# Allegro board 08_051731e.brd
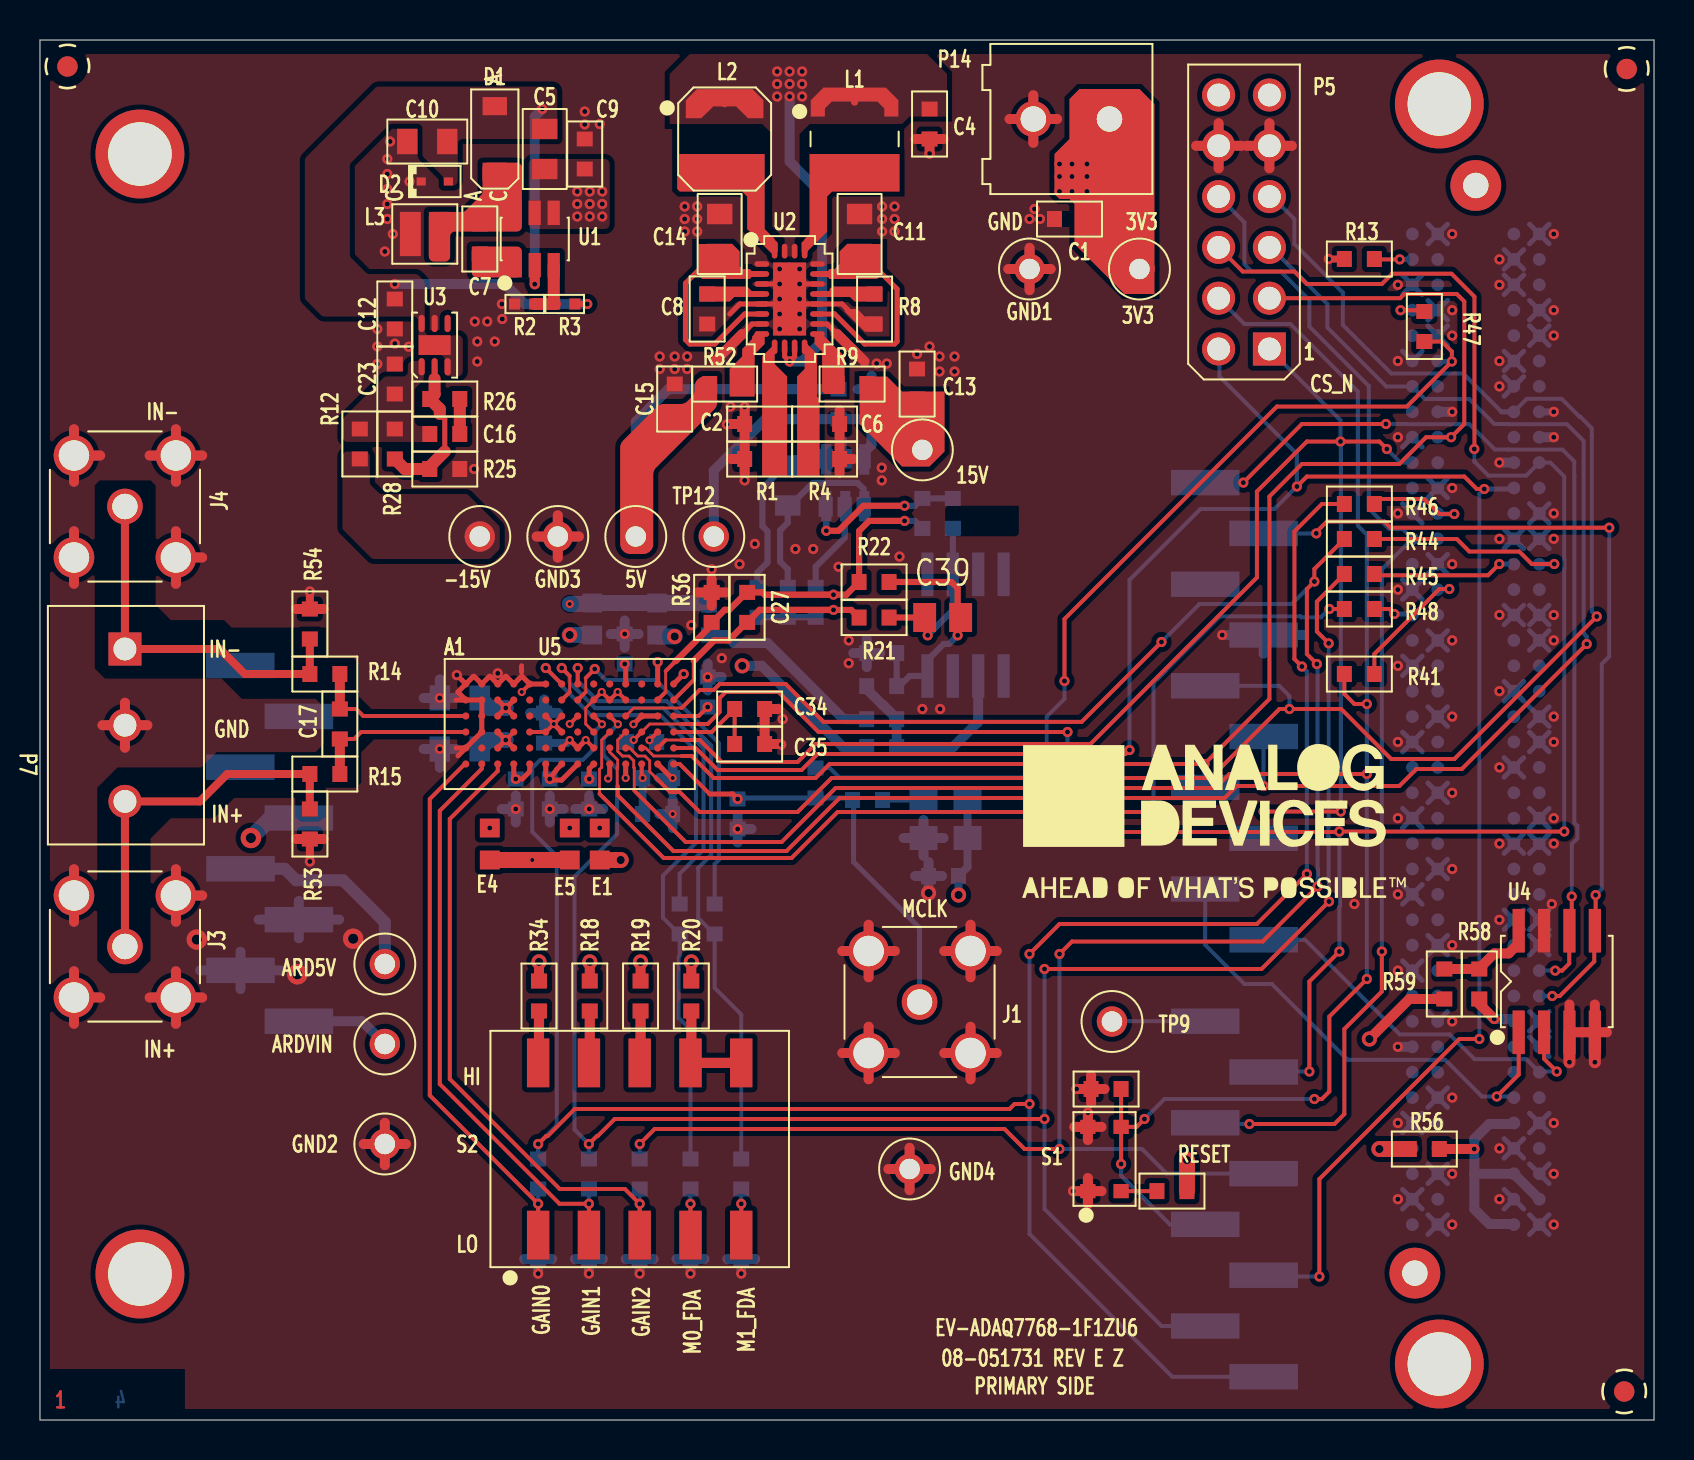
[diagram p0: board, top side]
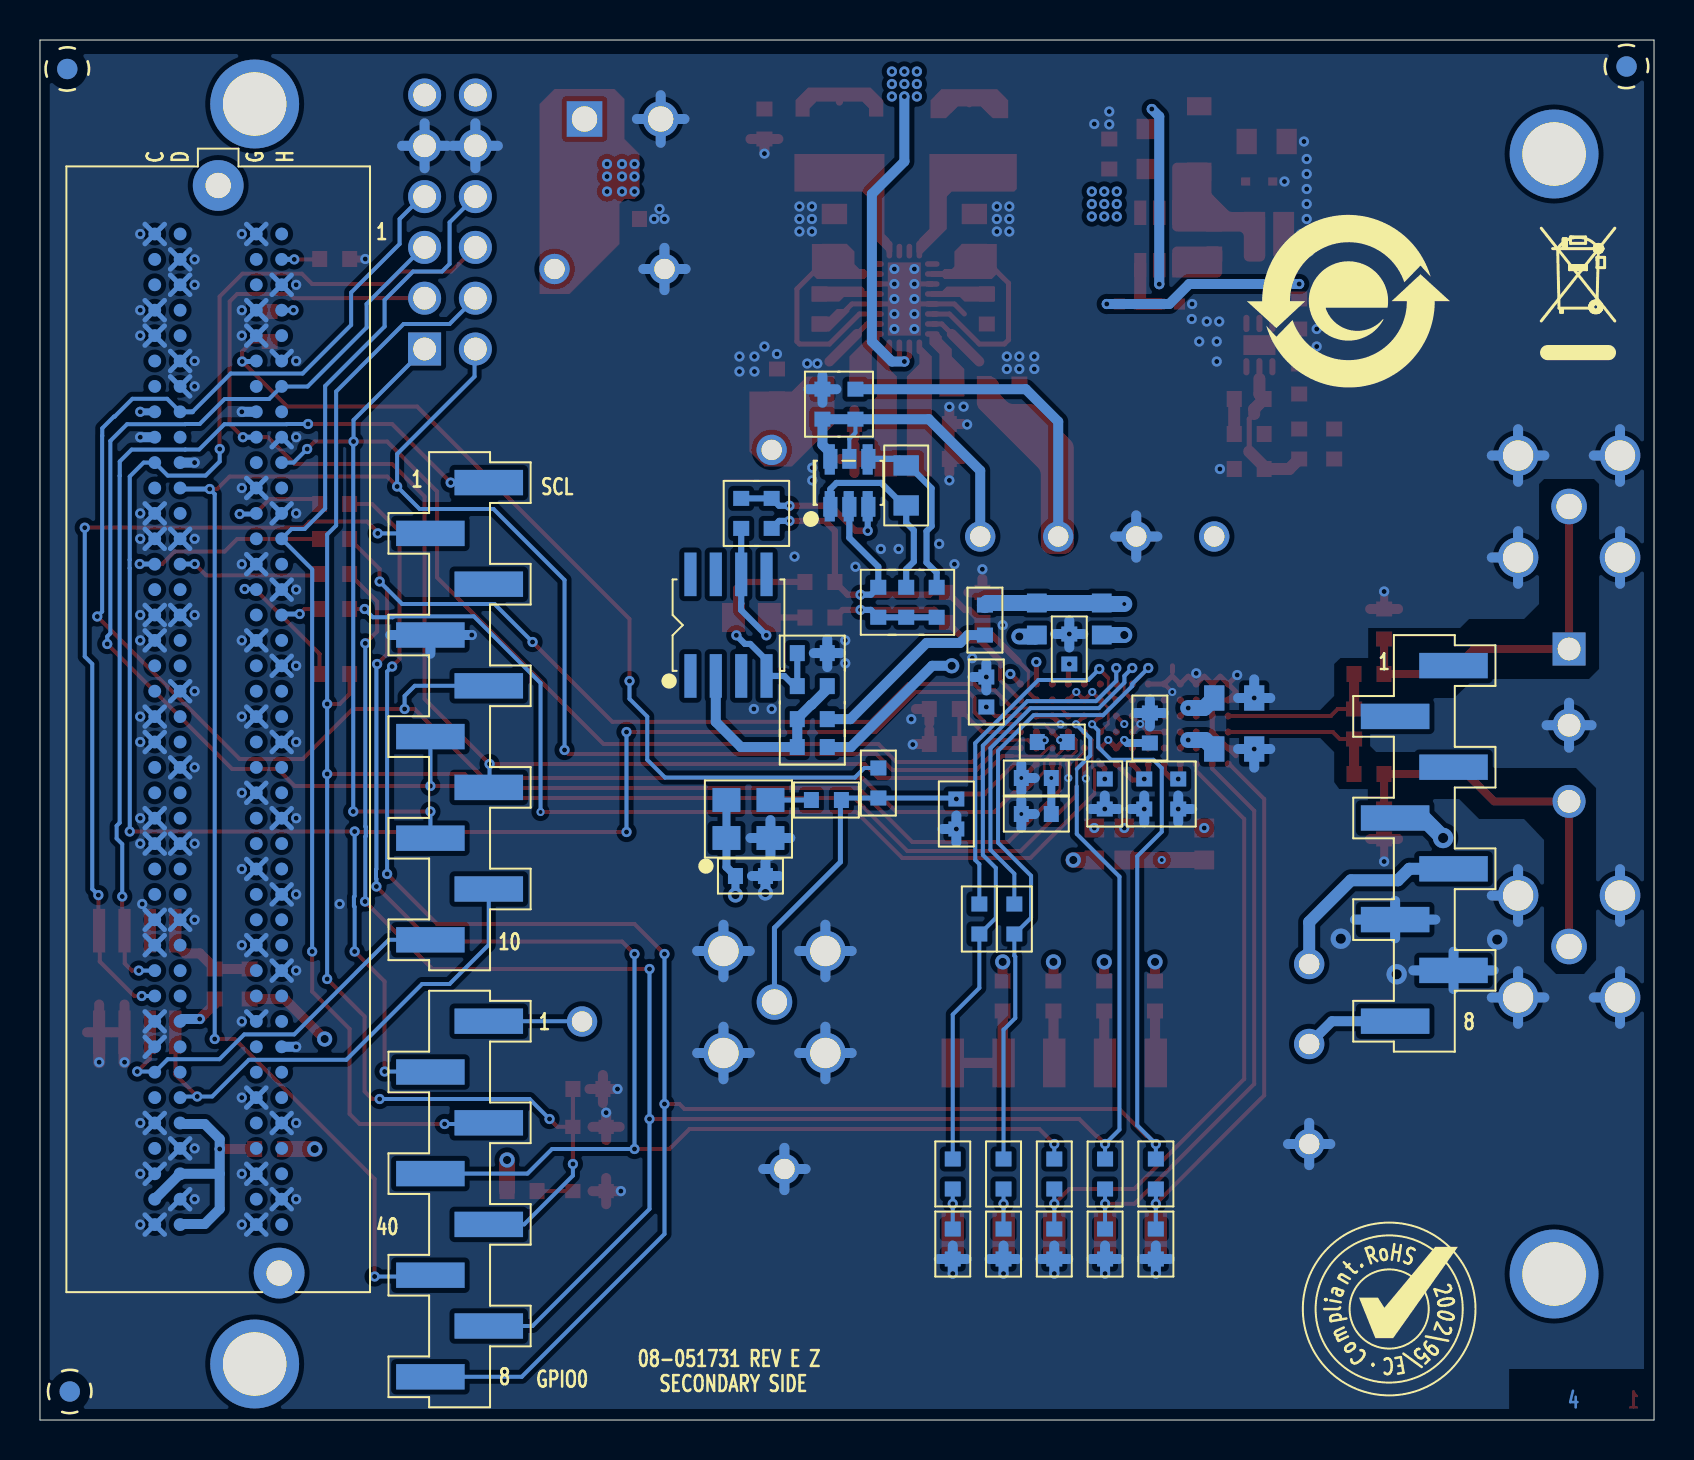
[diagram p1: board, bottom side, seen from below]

Outline 80.74 x 69 mm; copper layers: TOP, L2_GND, L3_PWR, BOTTOM. Coordinates in mm from the lower left corner of the outline.
Outline path: 0,69 80.74,69 80.74,0 0,0 0,69

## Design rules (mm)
constraint set DEFAULT: 
net group GAIN0: nets GAIN0 GPIO0
net group GAIN1: nets GAIN1 GPIO1
net group GAIN2: nets GAIN2 GPIO2
net group IN-N: nets IN-N IN-P
net group M0: nets M0 UNNAMED_3_RES_I311_N1
net group M1: nets M1 UNNAMED_3_RES_I312_N1
net group SYNC_IN: nets SYNC_IN UNNAMED_6_CN8PA_I42_N1
net group -16V: nets UNNAMED_3_ADP2301_I180_FB
net group REF_N: nets +IN -IN REF_N REF_P UNNAMED_3_ADR45XX_I443_VOUT VOUT
net group UNNAMED_3_ADP7182V5_I211_ADJ: nets UNNAMED_3_ADP7182V5_I211_ADJ UNNAMED_3_ADP7182V5_I211_VOUT UNNAMED_3_CAP_I209_N1

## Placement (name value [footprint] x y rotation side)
A1  ADA4807-1ARJZ  [SOT23_6-2]  40.25 46.86 180 bottom
A2  AD8628AUJZ  [TSOT-5]  40.28 46.86 180 bottom
ARD5V  RED  [CNKEY5001TP]  17.25 22.8 0 top
ARDVIN  RED  [CNKEY5001TP]  17.25 18.8 0 top
C1  1uF  [C0603]  51.5 60.05 180 top
C2  0.1uF  [C0603]  36 49.8 180 top
C3  TBD0603  [C0603]  34.9 30.3 270 bottom
C4  2.2uF  [C0603]  44.5 64.8 270 top
C5  1uF  [C0805H60]  25.25 63.55 90 top
C6  0.1uF  [C0603]  39.25 49.8 0 top
C7  0.1uF  [C0603]  22 59.05 90 top
C8  0.1uF  [C0603]  33.38 55.55 90 top
C9  1uF  [C0603]  27.25 63.3 90 top
C10  4.7uF  [C0805H53]  19.38 63.93 0 top
C11  10uF  [C0805H60]  41 59.3 90 top
C12  2.2uF  [C0603]  17.75 55.3 270 top
C13  2.2uF  [C0603]  43.88 51.8 90 top
C14  10uF  [C0805H60]  34 59.3 90 top
C15  2.2uF  [C0603]  31.75 51.05 90 top
C16  0.1uF  [C0603]  20.25 49.3 180 top
C17  TBD0603  [C0603]  15 34.8 270 top
C18  1uF  [C0805H60]  21 33.55 180 bottom
C19  1uF  [C0805H60]  21 36.1 180 bottom
C20  0.1uF  [C0603]  41.6 50.79 90 bottom
C21  TBD0603  [C0603]  25.5 31.3 270 bottom
C22  TBD0603  [C0603]  23.8 31.3 270 bottom
C23  2.2uF  [C0603]  17.75 52.05 90 top
C24  TBD0603  [C0603]  25.22 34.6 90 bottom
C25  0.1uF  [C0603]  45.2 27.2 180 bottom
C26  TBD0603  [C0603]  38.8 40.89 90 bottom
C27  2.2uF  [C0603]  35.38 40.63 90 top
C28  TBD0603  [C0603]  29.25 38.55 90 bottom
C29  TBD0603  [C0603]  33.4 36.4 90 bottom
C30  0.1uF  [C0603]  27.48 31.3 90 bottom
C34  0.1uF  [C0603]  35.5 35.55 0 top
C35  1uF  [C0603]  35.5 33.8 0 top
C36  0.1uF  [C0603]  30.9 30.3 0 bottom
C38  1uF  [C0603]  30.9 32.1 0 bottom
C39  1uF  [C0805]  45.16 40.12 0 top
C40  1uF  [C0603]  42.11 36.69 0 bottom
C44  0.1uF  [C0603]  53.33 16.55 180 top
C53  TBD0603  [C0603]  44.14 45.33 270 bottom
C54  3.9uF  [C0805H53]  37.41 46.73 270 bottom
D1  MBR0520LT1G  [SOD123-2]  22.75 64.05 90 top
D2  RB520S30T5G  [SOD523]  19.75 61.93 0 top
E1  1000OHM AT 100MEGHz  [L0603]  28 28.8 270 top
E2  1000OHM AT 100MEGHz  [L0603]  27.62 40.05 90 bottom
E3  1000OHM AT 100MEGHz  [L0603]  30.88 40.05 90 bottom
E4  1000OHM AT 100MEGHz  [L0603]  22.5 28.8 270 top
E5  1000OHM AT 100MEGHz  [L0603]  26.5 28.8 270 top
GND1  BLK  [CNKEY5001TP]  49.5 57.55 0 top
GND2  BLK  [CNKEY5001TP]  17.25 13.8 0 top
GND3  BLK  [CNKEY5001TP]  25.9 44.17 0 top
GND4  BLK  [CNKEY5001TP]  43.5 12.55 0 top
J1  1-1337482-0  [CNBNCSQ276H299]  44 20.9 0 top
J3  1-1337482-0  [CNBNCSQ276H299]  4.25 23.68 0 top
J4  1-1337482-0  [CNBNCSQ276H299]  4.25 45.68 0 top
L1  10UH  [LSMSQ154H71]  40.75 64.05 270 top
L2  6.8UH  [LSMSQ154H71_A]  34.25 64.05 270 top
L3  10UH  [LSMSQ79H57]  19.25 59.3 180 top
NOREF  -  []  0 69 0 top
NOREF#2  -  []  -43.1 -77.99 0 top
NOREF#3  -  []  80.74 0 90 top
NOREF#4  -  [unnamed#2]  79.38 67.55 0 top
NOREF#5  -  [unnamed#2]  5 7.3 0 top
NOREF#6  -  []  80.74 0 90 top
NOREF#7  -  []  80.74 0 0 top
NOREF#8  -  []  0 0 0 top
NOREF#9  -  [unnamed#2]  1.38 67.68 0 top
NOREF#10  -  []  309.56 73.44 0 top
NOREF#11  -  []  80.74 69 180 top
NOREF#12  -  []  0 0 0 top
NOREF#13  -  [unnamed#2]  79.25 1.43 0 top
NOREF#14  -  [unnamed#2]  70 2.8 0 top
NOREF#15  -  []  40.46 86.48 0 top
NOREF#16  -  []  0 0 0 top
NOREF#17  -  [unnamed#2]  70 65.8 0 top
NOREF#18  -  []  5 7.3 0 top
NOREF#19  -  []  0 69 270 top
NOREF#20  -  []  58.75 29.93 0 top
NOREF#21  -  []  0 69 0 top
NOREF#22  -  []  -43.1 -77.99 0 top
NOREF#23  -  [unnamed#2]  5 63.3 0 top
NOREF#24  -  []  5 7.3 0 top
NOREF#25  -  []  96.46 69.08 0 top
NOREF#26  -  [unnamed#2]  79.38 67.55 180 bottom
NOREF#27  -  [unnamed#2]  1.38 67.68 180 bottom
NOREF#28  -  []  15.29 55.94 180 bottom
NOREF#29  -  []  4 53.05 180 bottom
NOREF#30  -  []  13.25 5.55 180 bottom
NOREF#31  -  [unnamed#2]  79.25 1.43 180 bottom
P1  ASP-134604-01  [CNSAMTECASP-134604-01]  71.83 34.54 270 bottom
P2  TSM-108-04-T-SV  [CNSMMHDR2X4L800W100H293]  11.49 28.83 270 bottom
P3  TSM-110-04-T-SV  [CNSMMHDR2X5L1000W100H293]  59.75 35.44 270 bottom
P4  TSM-108-04-T-SV  [CNSMMHDR2X4L800W100H293]  59.75 11.05 270 bottom
P5  TSW-106-08-G-D  [CNHDR2X6H330LD35]  61.5 53.55 90 top
P7  1727023  [CNHDR1X3H335]  4.25 38.55 270 top
P14  CTB0308/2  [CNCAMDENCTB0308_2]  53.5 65.05 180 top
R1  105K  [R0603]  36 48.05 180 top
R2  68.1K  [R0402]  24.25 55.8 0 top
R3  3.57K  [R0402]  26.25 55.8 0 top
R4  300K  [R0603]  39.25 48.05 0 top
R5  0  [R0603]  27.46 12.3 90 bottom
R6  0  [R0603]  24.92 12.3 90 bottom
R7  0  [R0603]  30 12.3 90 bottom
R8  100K  [R0603]  41.75 55.55 270 top
R9  0  [R0603]  40.62 51.8 0 top
R10  0  [R0603]  35.08 12.3 90 bottom
R11  0  [R0603]  32.54 12.3 90 bottom
R12  0  [R0603]  16 48.8 270 top
R13  0  [R0603]  66 58.05 0 top
R14  0  [R0603]  14.25 37.3 0 top
R15  0  [R0603]  14.25 32.3 0 top
R16  0  [R0603]  32 25.05 270 bottom
R17  0  [R0603]  33.75 25.05 270 bottom
R18  1K  [R0603]  27.5 21.2 270 top
R19  1K  [R0603]  30.04 21.2 270 top
R20  1K  [R0603]  32.58 21.2 270 top
R21  11  [R0603]  41.73 40.12 180 top
R22  0  [R0603]  41.73 41.9 0 top
R23  0  [R0603]  42.11 35.04 0 bottom
R24  10K  [R0603]  56.62 11.44 0 top
R25  13K  [R0603]  20.25 47.55 0 top
R26  13K  [R0603]  20.25 51.05 0 top
R27  0  [R0603]  33.47 40 90 bottom
R28  147K  [R0603]  17.75 48.8 90 top
R29  20K  [R0603]  24.92 8.8 270 bottom
R30  20K  [R0603]  27.46 8.8 270 bottom
R31  20K  [R0603]  30 8.8 270 bottom
R32  20K  [R0603]  32.54 8.8 270 bottom
R33  20K  [R0603]  35.08 8.8 270 bottom
R34  1K  [R0603]  24.96 21.2 270 top
R35  0  [R0603]  39.95 50.79 90 bottom
R36  0  [R0603]  33.6 40.63 270 top
R37  0  [R0603]  38.8 31.85 270 bottom
R38  0  [R0603]  41.4 31 0 bottom
R40  0  [R0603]  30.1 33.9 180 bottom
R41  1K  [R0603]  66 37.3 180 top
R44  1K  [R0603]  66 44.05 180 top
R45  1K  [R0603]  66 42.3 180 top
R46  1K  [R0603]  66 45.8 180 top
R47  0  [R0603]  69.25 54.68 270 top
R48  1K  [R0603]  66 40.55 180 top
R49  0  [R0603]  42.11 38.35 0 bottom
R52  0  [R0603]  34.25 51.8 180 top
R53  TBD0603  [R0603]  13.5 29.8 270 top
R54  TBD0603  [R0603]  13.5 39.8 90 top
R55  1K  [R0603]  45.66 45.33 90 bottom
R56  0  [R0603]  69.25 13.55 0 top
R58  0  [R0603]  72 21.8 90 top
R59  TBD0603  [R0603]  70.25 21.8 270 top
R60  0  [R0603]  42.11 33.65 0 bottom
R66  1K  [R0603]  35.88 40.89 270 bottom
R67  100  [R0603]  37.41 40.89 270 bottom
S1  PTS830 GM140 SMTR LFS  [SWSML102W120H59]  53.25 13.05 0 top
S2  219-5MST  [SWCTS219]  30 13.55 0 top
TP9  RED  [CNKEY5001TP]  53.62 19.93 0 top
TP12  BLK  [CNKEY5001TP]  33.71 44.18 180 top
U1  ADP2300AUJZ  [TSOT23_6]  24.75 59.05 0 top
U2  LT3095IUDD#PBF  [QFN24_5X3_PAD3_65X1_65]  37.5 56.05 270 top
U3  ADP7182ACPZN  [DFN6_2X2_PAD1_6X1]  19.74 53.75 0 top
U4  M24C02-RMN6TP  [SO8]  75.88 21.93 0 top
U5  ADAQ7768-1BBCZ-V2  [BGA84_6X12]  26.5 34.8 270 top
U6  ADR4540BRZ  [SO8]  46.3 39.74 180 bottom
UNK3V3  BLK  [CNKEY5001TP]  55 57.55 0 top
UNK5V  BLK  [CNKEY5001TP]  29.8 44.17 270 top
UNK15V  BLK  [CNKEY5001TP]  44.14 48.51 270 top
UNK-15V  BLK  [CNKEY5001TP]  22 44.18 270 top
Y1  16.384MEGHZ  [YSML126W98H31]  45.3 30.05 180 bottom

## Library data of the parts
A1 = ADA4807_1: User Part Number: UPN; Tolerance: N/A; alternate symbols: (); part number: ADA4807_1_SM-ADA4807-1ARJZ,E024029,SOT23_6-2; tolerance: N/A
A2 = AD8628_V2: User Part Number: UPN; Tolerance: N/A; alternate symbols: (); part number: AD8628_V2_SM-AD8628AUJZ,E020512,TSOT-5; tolerance: N/A
ARD5V ARDVIN TP9 = CNTP1P: Tolerance: N/A; User Part Number: UPN; alternate symbols: (); part number: CNTP1P_TH-RED,E016323,CNKEY5001TP; tolerance: N/A
C1 C9 C35 C38 = CAP: User Part Number: UPN; Tolerance: 10; alternate symbols: (C0603L); part number: CAP_SM-1UF,10V,10,E024444,C0603; tolerance: 10; signal model: DEFAULT_CAPACITOR_1e+06pF_1_2
C2 C6-C8 C16 C25 C34 C36 C44 = CAP: User Part Number: UPN; Tolerance: 10; alternate symbols: (C0603L); part number: CAP_SM-0.1UF,25V,10,E013746,C0603; tolerance: 10
C3 C17 C21 C22 C24 C26 C28 C29 C53 = CAP: User Part Number: UPN; alternate symbols: (C0603L,C0603L_ALT); part number: CAP_SM-TBD0603,TBD0603,TBD0603,E000382,C0603; signal model: DEFAULT_CAPACITOR_0.001pF_1_2
C4 C15 = CAP: User Part Number: UPN; Tolerance: 10; alternate symbols: (C0603L); part number: CAP_SM-2.2UF,10V,10,E015288,C0603; tolerance: 10; signal model: DEFAULT_CAPACITOR_2.2e+06pF_1_2
C5 C18 C19 = CAP: User Part Number: UPN; Tolerance: 10; alternate symbols: (); part number: CAP_SM-1UF,25V,10,E007664,C0805H60; tolerance: 10; signal model: DEFAULT_CAPACITOR_1e+06pF_1_2
C10 = CAP: User Part Number: UPN; Tolerance: 10; alternate symbols: (); part number: CAP_SM-4.7UF,25V,10,E025752,C0805H53; tolerance: 10; signal model: DEFAULT_CAPACITOR_4.7e+06pF_1_2
C11 C14 = CAP: User Part Number: UPN; Tolerance: 10; alternate symbols: (); part number: CAP_SM-10UF,25V,10,E026259,C0805H60; tolerance: 10
C12 C13 C23 = CAP: User Part Number: UPN; Tolerance: 10; alternate symbols: (C0603L); part number: CAP_SM-2.2UF,50V,10,E024995,C0603; tolerance: 10; signal model: DEFAULT_CAPACITOR_2.2e+06pF_1_2
C20 = CAP: User Part Number: UPN; Tolerance: 10; alternate symbols: (C0603L); part number: CAP_SM-0.1UF,25V,10,E013746,C0603; tolerance: 10; signal model: DEFAULT_CAPACITOR_10000pF_2_1
C27 = CAP: User Part Number: UPN; Tolerance: 10; alternate symbols: (C0603L); part number: CAP_SM-2.2UF,10V,10,E010426,C0603; tolerance: 10
C30 = CAP: User Part Number: UPN; Tolerance: 10; alternate symbols: (C0603L); part number: CAP_SM-0.1UF,50V,10,E011865,C0603; tolerance: 10
C39 = CAP: User Part Number: UPN; Tolerance: 10; alternate symbols: (C0805L); part number: CAP_SM-1UF,100V,10,E014208,C0805; tolerance: 10
C40 = CAP: User Part Number: UPN; Tolerance: 10; alternate symbols: (C0603L); part number: CAP_SM-1UF,10V,10,E024444,C0603; tolerance: 10
C54 = CAP: User Part Number: UPN; Tolerance: 10; alternate symbols: (); part number: CAP_SM-3.9UF,10V,10,E031990,C0805H53; tolerance: 10; signal model: DEFAULT_CAPACITOR_3.9e+06pF_1_2
D1 = DIOSCHOTTKY: User Part Number: UPN; Tolerance: N/A; alternate symbols: (); part number: DIOSCHOTTKY_SM-MBR0520LT1G,20V,N/A,E019662,SOD123-2; tolerance: N/A
D2 = DIOSCHOTTKY: Tolerance: N/A; User Part Number: UPN; alternate symbols: (); part number: DIOSCHOTTKY_SM-RB520S30T5G,30V,N/A,E036017,SOD523; tolerance: N/A
E1-E5 = FERRITE: User Part Number: UPN; Tolerance: 25; alternate symbols: (L0603L); part number: FERRITE_SM-1000OHM AT 100MEGHZ,25,E027309,L0603; tolerance: 25
GND1-GND4 TP12 UNK3V3 UNK5V UNK15V UNK-15V = CNTP1P: Tolerance: N/A; User Part Number: UPN; alternate symbols: (); part number: CNTP1P_TH-BLK,E005347,CNKEY5001TP; tolerance: N/A
J1 J3 J4 = CNBNC5P: Tolerance: N/A; User Part Number: UPN; alternate symbols: (); part number: CNBNC5P_TH-1-1337482-0,E013941,CNBNCSQ276H299; tolerance: N/A
L1 = IND: User Part Number: UPN; Tolerance: 20; alternate symbols: (); part number: IND_SM-10UH,20,E017851,LSMSQ154H71; tolerance: 20; signal model: DEFAULT_INDUCTOR_10000nH_1_2
L2 = IND: User Part Number: UPN; Tolerance: 20; alternate symbols: (); part number: IND_SM-6.8UH,20,E027661,LSMSQ154H71_A; tolerance: 20; signal model: DEFAULT_INDUCTOR_6800nH_1_2
L3 = IND: Tolerance: 20; User Part Number: UPN; alternate symbols: (); part number: IND_SM-10UH,20,E028343,LSMSQ79H57; tolerance: 20; signal model: DEFAULT_INDUCTOR_10000nH_1_2
P1 = CN160P_CDGH_V2: User Part Number: UPN; Tolerance: N/A; alternate symbols: (CNSAMTECASP-134604-01_KITTRF,CNSAMTECASP-134604-01_EVKP); part number: CN160P_CDGH_V2_SM-ASP-134604-01,E011383,CNSAMTECASP-134604-01; tolerance: N/A
P2 = CN8P_A: User Part Number: UPN; Tolerance: N/A; alternate symbols: (); part number: CN8P_A_SM-TSM-108-04-T-SV,E028029,CNSMMHDR2X4L800W100H293; tolerance: N/A
P3 = CN10P: User Part Number: UPN; Tolerance: N/A; alternate symbols: (); part number: CN10P_SM-TSM-110-04-T-SV,E028030,CNSMMHDR2X5L1000W100H293; tolerance: N/A
P4 = CN8P_A: User Part Number: UPN; Tolerance: N/A; alternate symbols: (); part number: CN8P_A_SM-TSM-108-04-T-SV,E028029,CNSMMHDR2X4L800W100H293; tolerance: N/A; signal model: DEFAULT_RESISTOR_1.80328e+06OHM_2_1
P5 = CN12P_V3: Tolerance: N/A; User Part Number: UPN; alternate symbols: (); part number: CN12P_V3_TH-TSW-106-08-G-D,E000735,CNHDR2X6H330LD35; tolerance: N/A
P7 = CN3P: Tolerance: N/A; User Part Number: UPN; alternate symbols: (); part number: CN3P_TH-1727023,E015204,CNHDR1X3H335; tolerance: N/A
P14 = CN2P: User Part Number: UPN; Tolerance: N/A; alternate symbols: (); part number: CN2P_TH-CTB0308/2,E026049,CNCAMDENCTB0308_2; tolerance: N/A
R1 = RES: User Part Number: UPN; Tolerance: 1; alternate symbols: (R0603L); part number: RES_SM-105K,E019711,1/10W,1,R0603; tolerance: 1; signal model: DEFAULT_RESISTOR_105000OHM_1_2
R2 = RES: User Part Number: UPN; Tolerance: 1; alternate symbols: (R0402L); part number: RES_SM-68.1K,E014436,1/10W,1,R0402; tolerance: 1; signal model: DEFAULT_RESISTOR_68100OHM_1_2
R3 = RES: User Part Number: UPN; Tolerance: 1; alternate symbols: (R0402L); part number: RES_SM-3.57K,E007344,1/10W,1,R0402; tolerance: 1; signal model: DEFAULT_RESISTOR_3570OHM_1_2
R4 = RES: User Part Number: UPN; Tolerance: 0.1; alternate symbols: (R0603L); part number: RES_SM-300K,E024299,1/10W,0.1,R0603; tolerance: 0.1; signal model: DEFAULT_RESISTOR_300000OHM_1_2
R5 = RES: User Part Number: UPN; Tolerance: JUMPER; alternate symbols: (R0603L); part number: RES_SM-0,E027148,1/4W,JUMPER,R0603; tolerance: JUMPER; signal model: DEFAULT_RESISTOR_75.000000OHM_2_1
R6 R7 R11 = RES: User Part Number: UPN; Tolerance: JUMPER; alternate symbols: (R0603L); part number: RES_SM-0,E027148,1/4W,JUMPER,R0603; tolerance: JUMPER; signal model: DEFAULT_RESISTOR_10000OHM_2_1
R8 = RES: User Part Number: UPN; Tolerance: 1; alternate symbols: (R0603L); part number: RES_SM-100K,E030871,1/10W,1,R0603; tolerance: 1; signal model: DEFAULT_RESISTOR_100000OHM_1_2
R9 R12-R15 R22 R23 R27 R35-R37 R40 R49 R52 R56 R58 R60 = RES: User Part Number: UPN; Tolerance: JUMPER; alternate symbols: (R0603L); part number: RES_SM-0,E006826,1/10W,JUMPER,R0603; tolerance: JUMPER
R10 = RES: User Part Number: UPN; Tolerance: JUMPER; alternate symbols: (R0603L); part number: RES_SM-0,E027148,1/4W,JUMPER,R0603; tolerance: JUMPER; signal model: DEFAULT_RESISTOR_1e+07OHM_2_1
R16 R17 R38 R47 = RES: User Part Number: UPN; Tolerance: JUMPER; alternate symbols: (R0603L); part number: RES_SM-0,E027148,1/4W,JUMPER,R0603; tolerance: JUMPER
R18-R20 R34 R41 R44-R46 R48 = RES: User Part Number: UPN; Tolerance: 1; alternate symbols: (R0603L); part number: RES_SM-1K,E003678,1/10W,1,R0603; tolerance: 1
R21 = RES: User Part Number: UPN; Tolerance: 1; alternate symbols: (R0603L); part number: RES_SM-11,E003708,1/10W,1,R0603; tolerance: 1
R24 = RES: User Part Number: UPN; Tolerance: 1; alternate symbols: (R0603L); part number: RES_SM-10K,E003671,1/10W,1,R0603; tolerance: 1; signal model: DEFAULT_RESISTOR_10000OHM_1_2
R25 R26 = RES: User Part Number: UPN; Tolerance: 1; alternate symbols: (R0603L); part number: RES_SM-13K,E020173,1/10W,1,R0603; tolerance: 1; signal model: DEFAULT_RESISTOR_13000OHM_1_2
R28 = RES: User Part Number: UPN; Tolerance: 0.5; alternate symbols: (R0603L); part number: RES_SM-147K,E006436,1/16W,0.5,R0603; tolerance: 0.5; signal model: DEFAULT_RESISTOR_147000OHM_1_2
R29-R33 = RES: User Part Number: UPN; Tolerance: 1; alternate symbols: (R0603L); part number: RES_SM-20K,E017927,1/10W,1,R0603; tolerance: 1; signal model: DEFAULT_RESISTOR_20000OHM_1_2
R53 R54 R59 = RES: User Part Number: UPN; alternate symbols: (R0603L); part number: RES_SM-TBD0603,E004050,TBD0603,TBD0603,R0603; signal model: DEFAULT_RESISTOR_0.001OHM_1_2
R55 R66 = RES: User Part Number: UPN; Tolerance: 0.1; alternate symbols: (R0603L); part number: RES_SM-1K,E003953,1/10W,0.1,R0603; tolerance: 0.1; signal model: DEFAULT_RESISTOR_1000.000000OHM_1_2
R67 = RES: User Part Number: UPN; Tolerance: 1; alternate symbols: (R0603L); part number: RES_SM-100,E003668,1/10W,1,R0603; tolerance: 1; signal model: DEFAULT_RESISTOR_100.000000OHM_1_2
S1 = SWSPST4P_V2: User Part Number: UPN; Tolerance: N/A; alternate symbols: (); part number: SWSPST4P_V2_SM-PTS830 GM140 SMTR LFS,E025176,SWSML102W120H59; tolerance: N/A
S2 = SWITCH5: Tolerance: N/A; User Part Number: UPN; alternate symbols: (); part number: SWITCH5_SM-219-5MST,E006279,SWCTS219; tolerance: N/A
U1 = ADP2301: User Part Number: UPN; Tolerance: N/A; alternate symbols: (); part number: ADP2301_SM-ADP2300AUJZ,E013639,TSOT23_6; tolerance: N/A
U2 = LINLT3095: User Part Number: UPN; Tolerance: N/A; alternate symbols: (); part number: LINLT3095_SM-LT3095IUDD#PBF,E031115,QFN24_5X3_PAD3_65X1_65; tolerance: N/A
U3 = ADP7182_V5: Tolerance: N/A; User Part Number: UPN; alternate symbols: (); part number: ADP7182_V5_SM-ADP7182ACPZN,E024308,DFN6_2X2_PAD1_6X1; tolerance: N/A
U4 = ICM24CXX: User Part Number: UPN; Tolerance: N/A; alternate symbols: (); part number: ICM24CXX_SM-M24C02-RMN6TP,E018349,SO8; tolerance: N/A
U5 = ADAQ7768_1_V2: Tolerance: N/A; User Part Number: UPN; alternate symbols: (); part number: ADAQ7768_1_V2_SM-ADAQ7768-1BBCZ-V2,E034273,BGA84_6X12; tolerance: N/A
U6 = ADR45XX: User Part Number: UPN; Tolerance: N/A; alternate symbols: (); part number: ADR45XX_SM-ADR4540BRZ,E017544,SO8; tolerance: N/A
Y1 = XTALOSC4P_V3: Tolerance: N/A; User Part Number: UPN; alternate symbols: (); part number: XTALOSC4P_V3_SM-16.384MEGHZ,E031111,YSML126W98H31; tolerance: N/A

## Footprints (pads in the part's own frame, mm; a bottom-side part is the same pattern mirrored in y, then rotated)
BGA84_6X12
  round 0.356 smd: A1(-2,-5.2) A2(-2,-4.4) A3(-2,-3.6) A4(-2,-2.8) A5(-2,-2) A6(-2,-1.2) A7(-2,-0.4) A8(-2,0.4) A9(-2,1.2) A10(-2,2) A11(-2,2.8) A12(-2,3.6) A13(-2,4.4) A14(-2,5.2) B1(-1.2,-5.2) B2(-1.2,-4.4) B3(-1.2,-3.6) B4(-1.2,-2.8) B5(-1.2,-2) B6(-1.2,-1.2) B7(-1.2,-0.4) B8(-1.2,0.4) B9(-1.2,1.2) B10(-1.2,2) B11(-1.2,2.8) B12(-1.2,3.6) B13(-1.2,4.4) B14(-1.2,5.2) C1(-0.4,-5.2) C2(-0.4,-4.4) C3(-0.4,-3.6) C4(-0.4,-2.8) C5(-0.4,-2) C6(-0.4,-1.2) C7(-0.4,-0.4) C8(-0.4,0.4) C9(-0.4,1.2) C10(-0.4,2) C11(-0.4,2.8) C12(-0.4,3.6) C13(-0.4,4.4) C14(-0.4,5.2) D1(0.4,-5.2) D2(0.4,-4.4) D3(0.4,-3.6) D4(0.4,-2.8) D5(0.4,-2) D6(0.4,-1.2) D7(0.4,-0.4) D8(0.4,0.4) D9(0.4,1.2) D10(0.4,2) D11(0.4,2.8) D12(0.4,3.6) D13(0.4,4.4) D14(0.4,5.2) E1(1.2,-5.2) E2(1.2,-4.4) E3(1.2,-3.6) E4(1.2,-2.8) E5(1.2,-2) E6(1.2,-1.2) E7(1.2,-0.4) E8(1.2,0.4) E9(1.2,1.2) E10(1.2,2) E11(1.2,2.8) E12(1.2,3.6) E13(1.2,4.4) E14(1.2,5.2) F1(2,-5.2) F2(2,-4.4) F3(2,-3.6) F4(2,-2.8) F5(2,-2) F6(2,-1.2) F7(2,-0.4) F8(2,0.4) F9(2,1.2) F10(2,2) F11(2,2.8) F12(2,3.6) F13(2,4.4) F14(2,5.2)
C0603
  rect 0.749x0.8 smd: 1(-0.75,0) 2(0.75,0)
C0805
  rect 1.143x1.448 smd: 1(-0.9,0) 2(0.9,0)
C0805H53
  rect 1.016x1.27 smd: 1(-1,0) 2(1,0)
C0805H60
  rect 1.016x1.27 smd: 1(-1,0) 2(1,0)
CNBNCSQ276H299
  round 1.78 hole 1.27: 1(0,0)
  round 2.03 hole 1.519: 2(-2.55,2.55) 3(2.55,2.55) 4(2.55,-2.55) 5(-2.55,-2.55)
CNCAMDENCTB0308_2
  rect 1.78x1.78 hole 1.27: 1(0,0)
  round 1.78 hole 1.27: 2(3.81,0)
CNHDR1X3H335
  rect 1.651x1.651 hole 1.141: 1(0,0)
  round 1.651 hole 1.141: 2(3.81,0) 3(7.62,0)
CNHDR2X6H330LD35
  rect 1.651x1.651 hole 1.141: 1(0,0)
  round 1.651 hole 1.141: 2(2.54,0) 3(5.08,0) 4(7.62,0) 5(10.16,0) 6(12.7,0) 7(0,2.54) 8(2.54,2.54) 9(5.08,2.54) 10(7.62,2.54) 11(10.16,2.54) 12(12.7,2.54)
CNKEY5001TP
  round 1.519 hole 1.021: 1(0,0)
CNSAMTECASP-134604-01
  round 2.54 hole 1.27 unplated: (-27.191,0) (27.191,3.048)
  round 0.64 smd: C1(-24.765,-3.175) C2(-23.495,-3.175) C3(-22.225,-3.175) C4(-20.955,-3.175) C5(-19.685,-3.175) C6(-18.415,-3.175) C7(-17.145,-3.175) C8(-15.875,-3.175) C9(-14.605,-3.175) C10(-13.335,-3.175) C11(-12.065,-3.175) C12(-10.795,-3.175) C13(-9.525,-3.175) C14(-8.255,-3.175) C15(-6.985,-3.175) C16(-5.715,-3.175) C17(-4.445,-3.175) C18(-3.175,-3.175) C19(-1.905,-3.175) C20(-0.635,-3.175) C21(0.635,-3.175) C22(1.905,-3.175) C23(3.175,-3.175) C24(4.445,-3.175) C25(5.715,-3.175) C26(6.985,-3.175) C27(8.255,-3.175) C28(9.525,-3.175) C29(10.795,-3.175) C30(12.065,-3.175) C31(13.335,-3.175) C32(14.605,-3.175) C33(15.875,-3.175) C34(17.145,-3.175) C35(18.415,-3.175) C36(19.685,-3.175) C37(20.955,-3.175) C38(22.225,-3.175) C39(23.495,-3.175) C40(24.765,-3.175) D1(-24.765,-1.905) D2(-23.495,-1.905) D3(-22.225,-1.905) D4(-20.955,-1.905) D5(-19.685,-1.905) D6(-18.415,-1.905) D7(-17.145,-1.905) D8(-15.875,-1.905) D9(-14.605,-1.905) D10(-13.335,-1.905) D11(-12.065,-1.905) D12(-10.795,-1.905) D13(-9.525,-1.905) D14(-8.255,-1.905) D15(-6.985,-1.905) D16(-5.715,-1.905) D17(-4.445,-1.905) D18(-3.175,-1.905) D19(-1.905,-1.905) D20(-0.635,-1.905) D21(0.635,-1.905) D22(1.905,-1.905) D23(3.175,-1.905) D24(4.445,-1.905) D25(5.715,-1.905) D26(6.985,-1.905) D27(8.255,-1.905) D28(9.525,-1.905) D29(10.795,-1.905) D30(12.065,-1.905) D31(13.335,-1.905) D32(14.605,-1.905) D33(15.875,-1.905) D34(17.145,-1.905) D35(18.415,-1.905) D36(19.685,-1.905) D37(20.955,-1.905) D38(22.225,-1.905) D39(23.495,-1.905) D40(24.765,-1.905) G1(-24.765,1.905) G2(-23.495,1.905) G3(-22.225,1.905) G4(-20.955,1.905) G5(-19.685,1.905) G6(-18.415,1.905) G7(-17.145,1.905) G8(-15.875,1.905) G9(-14.605,1.905) G10(-13.335,1.905) G11(-12.065,1.905) G12(-10.795,1.905) G13(-9.525,1.905) G14(-8.255,1.905) G15(-6.985,1.905) G16(-5.715,1.905) G17(-4.445,1.905) G18(-3.175,1.905) G19(-1.905,1.905) G20(-0.635,1.905) G21(0.635,1.905) G22(1.905,1.905) G23(3.175,1.905) G24(4.445,1.905) G25(5.715,1.905) G26(6.985,1.905) G27(8.255,1.905) G28(9.525,1.905) G29(10.795,1.905) G30(12.065,1.905) G31(13.335,1.905) G32(14.605,1.905) G33(15.875,1.905) G34(17.145,1.905) G35(18.415,1.905) G36(19.685,1.905) G37(20.955,1.905) G38(22.225,1.905) G39(23.495,1.905) G40(24.765,1.905) H1(-24.765,3.175) H2(-23.495,3.175) H3(-22.225,3.175) H4(-20.955,3.175) H5(-19.685,3.175) H6(-18.415,3.175) H7(-17.145,3.175) H8(-15.875,3.175) H9(-14.605,3.175) H10(-13.335,3.175) H11(-12.065,3.175) H12(-10.795,3.175) H13(-9.525,3.175) H14(-8.255,3.175) H15(-6.985,3.175) H16(-5.715,3.175) H17(-4.445,3.175) H18(-3.175,3.175) H19(-1.905,3.175) H20(-0.635,3.175) H21(0.635,3.175) H22(1.905,3.175) H23(3.175,3.175) H24(4.445,3.175) H25(5.715,3.175) H26(6.985,3.175) H27(8.255,3.175) H28(9.525,3.175) H29(10.795,3.175) H30(12.065,3.175) H31(13.335,3.175) H32(14.605,3.175) H33(15.875,3.175) H34(17.145,3.175) H35(18.415,3.175) H36(19.685,3.175) H37(20.955,3.175) H38(22.225,3.175) H39(23.495,3.175) H40(24.765,3.175)
CNSMMHDR2X4L800W100H293
  rect 1.27x3.429 smd: 1(-8.89,1.46) 2(-6.35,-1.46) 3(-3.81,1.46) 4(-1.27,-1.46) 5(1.27,1.46) 6(3.81,-1.46) 7(6.35,1.46) 8(8.89,-1.46)
CNSMMHDR2X5L1000W100H293
  rect 1.27x3.429 smd: 1(-11.43,1.46) 2(-8.89,-1.46) 3(-6.35,1.46) 4(-3.81,-1.46) 5(-1.27,1.46) 6(1.27,-1.46) 7(3.81,1.46) 8(6.35,-1.46) 9(8.89,1.46) 10(11.43,-1.46)
DFN6_2X2_PAD1_6X1
  oval 0.305x0.864 smd: 1(-0.65,-1.082) 2(0,-1.082) 3(0.65,-1.082) 4(0.65,1.082) 5(0,1.082) 6(-0.65,1.082)
  rect 1.6x0.991 smd: PAD(0,0)
L0603
  rect 0.94x0.991 smd: 1(-0.8,0) 2(0.8,0)
LSMSQ79H57
  rect 1.041x2.21 smd: 1(-0.724,0) 2(0.724,0)
LSMSQ154H71
  custom 0.362x0.362 smd: 1(-1.847,0) 2(1.847,0)
LSMSQ154H71_A
  custom 0.362x0.362 smd: 1(-1.765,0) 2(1.765,0)
QFN24_5X3_PAD3_65X1_65
  oval 0.279x0.737 smd: 1(-1.75,-1.393) 2(-1.25,-1.393) 3(-0.75,-1.393) 4(-0.25,-1.393) 5(0.25,-1.393) 6(0.75,-1.393) 7(1.25,-1.393) 8(1.75,-1.393) 13(1.75,1.393) 14(1.25,1.393) 15(0.75,1.393) 16(0.25,1.393) 17(-0.25,1.393) 18(-0.75,1.393) 19(-1.25,1.393) 20(-1.75,1.393)
  oval 0.737x0.279 smd: 9(2.393,-0.75) 10(2.393,-0.25) 11(2.393,0.25) 12(2.393,0.75) 21(-2.393,0.75) 22(-2.393,0.25) 23(-2.393,-0.25) 24(-2.393,-0.75)
  rect 3.658x1.651 smd: PAD(0,0)
R0402
  rect 0.559x0.559 smd: 1(-0.508,0) 2(0.508,0)
R0603
  rect 0.749x0.8 smd: 1(-0.75,0) 2(0.75,0)
SO8
  rect 0.61x2.179 smd: 1(-1.905,-2.54) 2(-0.635,-2.54) 3(0.635,-2.54) 4(1.905,-2.54) 5(1.905,2.54) 6(0.635,2.54) 7(-0.635,2.54) 8(-1.905,2.54)
SOD123-2
  rect 0.909x1.219 smd: A(1.638,0) C(-1.638,0)
SOD523
  rect 0.457x0.406 smd: A(0.679,0) C(-0.679,0)
SOT23_6-2
  rect 0.711x0.991 smd: 1(-0.95,-1.2) 2(0,-1.2) 3(0.95,-1.2) 4(0.95,1.2) 5(0,1.2) 6(-0.95,1.2)
SWCTS219
  rect 1.12x2.441 smd: 1A(-5.08,-4.305) 1B(-5.08,4.305) 2A(-2.54,-4.305) 2B(-2.54,4.305) 3A(0,-4.305) 3B(0,4.305) 4A(2.54,-4.305) 4B(2.54,4.305) 5A(5.08,-4.305) 5B(5.08,4.305)
SWSML102W120H59
  rect 0.762x0.711 smd: 1(-0.831,-1.605) 2(-0.831,1.605) 3(0.831,-1.605) 4(0.831,1.605)
TSOT23_6
  rect 0.61x1.219 smd: 1(-0.95,-1.31) 2(0,-1.31) 3(0.95,-1.31) 4(0.95,1.31) 5(0,1.31) 6(-0.95,1.31)
TSOT-5
  rect 0.51x1.519 smd: 1(-0.95,-1.17) 2(0,-1.17) 3(0.95,-1.17) 4(0.95,1.17) 5(-0.95,1.17)
unnamed#2
  round 1.021 smd: (0,0)
YSML126W98H31
  rect 1.397x1.194 smd: 1(-1.1,-0.95) 2(1.1,-0.95) 3(1.1,0.95) 4(-1.1,0.95)

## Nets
3V3: C1.1 C4.1 C5.1 C9.1 C25.1 E1.2(N2) L1.1 L2.1 P2.4 P5.6 P5.12(VCC2) P14.1 R18.1 R19.1 R20.1 R24.2(N2) R34.1 R56.1 R59.2(N2) U1.4 U1.5(VIN) U2.10 U2.11 U2.22 U2.23 U5.C8 UNK3V3.1 Y1.1 Y1.4(VDD)
3V3_AUX: P1.D32 R58.1
5V3: C15.1 R35.2(N2) R52.2(N2) R60.1 U5.B9 U5.B10 U5.B11 U5.D9 UNK5V.1
15V: C13.1 C18.1 R9.2(N2) U5.D3 U5.D4 U5.E3 U5.E4 UNK15V.1
-15V: C19.1 R12.2(N2) U5.B3 U5.B4 U5.C3 U5.C4 UNK-15V.1
-16V: C5.2(N2) C10.2(N2) C12.1 D1.A(P) D2.A(P) R3.2(N2) U1.2 U3.3 U3.6 U3.PAD
GND_SIGNAL: C1.2(N2) C2.2(N2) C3.2(N2) C4.2(N2) C6.2(N2) C8.1 C9.2(N2) C10.1 C11.2(N2) C12.2(N2) C13.2(N2) C14.2(N2) C15.2(N2) C18.2(N2) C19.2(N2) C20.2(N2) C21.2(N2) C22.2(N2) C23.2(N2) C24.2(N2) C25.2(N2) C28.2(N2) C29.2(N2) C30.1 C34.2(N2) C35.2(N2) C36.2(N2) C38.2(N2) C44.2(N2) D2.C GND1.1(N1) GND2.1(N1) GND3.1(N1) GND4.1(N1) J1.2 J1.3 J1.4 J1.5(SH4) J3.2 J3.3 J3.4 J3.5(SH4) J4.2 J4.3 J4.4 J4.5(SH4) L3.2(N2) P1.C1 P1.C4 P1.C5 P1.C8 P1.C9 P1.C12 P1.C13 P1.C16 P1.C17 P1.C20 P1.C21 P1.C24 P1.C25 P1.C28 P1.C29 P1.C32 P1.C33 P1.C36 P1.C38 P1.C40 P1.D2 P1.D3 P1.D6 P1.D7 P1.D10 P1.D13 P1.D16 P1.D19 P1.D22 P1.D25 P1.D28 P1.D37 P1.D39 P1.G1 P1.G4 P1.G5 P1.G8 P1.G11 P1.G14 P1.G17 P1.G20 P1.G23 P1.G26 P1.G29 P1.G32 P1.G35 P1.G38 P1.G40 P1.H3 P1.H6 P1.H9 P1.H12 P1.H15 P1.H18 P1.H21 P1.H24 P1.H27 P1.H30 P1.H33 P1.H36 P1.H39 P2.6 P2.7 P3.4 P5.5 P5.11 P7.2 P14.2(N2) R1.2(N2) R2.1 R4.2(N2) R8.2(N2) R13.1 R25.2(N2) R29.2(N2) R30.2(N2) R31.2(N2) R32.2(N2) R33.2(N2) R36.1 R49.1 R53.2(N2) R54.2(N2) S1.1 S1.2 U2.1 U2.3 U2.5 U2.7 U2.14 U2.16 U2.18(SYNC) U2.20 U2.PAD U3.5 U4.3 U4.4 U4.7(WC_N) U5.A1 U5.A2 U5.A3 U5.A4 U5.A5 U5.A6 U5.B1 U5.B2 U5.C2 U5.C6 U5.C7 U5.C12 U5.C13 U5.D2 U5.D5 U5.D6 U5.D7 U5.E1 U5.F10 U5.F11 U5.F13 Y1.2
VDD2_ADC: C29.1 E3.1 U5.A14 U5.C14
VDD2_PGA: C22.1 E4.1 U5.F4 U5.F5
VDD_ADC: C28.1 E2.1 U5.A11 U5.A13
VDD_FDA: C24.1 E5.1 U5.E7 U5.E8 U5.E9
VDD_IO: C30.2(N2) E1.1 U5.F9
+IN: A1.3 A2.3 C53.1 R55.2(N2)
+VS: A1.5 A1.6 A2.5 C20.1 R35.1 TP12.1(N1)
-IN: A1.4 A2.4 C54.1 R66.1
ARD_5V: ARD5V.1(N1) P2.5
ARD_VIN: ARDVIN.1(N1) P2.8(N8)
AREG_CAP: C34.1 C35.1 U5.D14
CS_GN: P1.H13 P4.3 P5.10
CS_N: P1.H10 P3.8 P5.1 U5.E13
DOUT_RDYB: P1.H7 P3.6 P5.3 U5.E10
DRDY: P1.D11 P4.6 P5.7 U5.E14
DREG_CAP: C36.1 C38.1 U5.F12
GA0: P1.C34 P3.10 U4.2
GA1: P1.D35 P3.9(N9) U4.1
GAIN0: R6.1 R29.1 S2.1A U5.F1
GAIN1: R5.1 R30.1 S2.2A U5.F2
GAIN2: R7.1 R31.1 S2.3A U5.F3
GPIO0: P4.8(N8) R6.2(N2) R46.2(N2) U5.C9
GPIO1: P4.7 R5.2(N2) R45.2(N2) U5.C10
GPIO2: P4.4 R7.2(N2) R44.2(N2) U5.C11
GPIO3: R48.2(N2) U5.D10
IN+: J3.1 P7.3(N3) R15.1 R53.1
IN-: J4.1 P7.1 R14.1 R54.1
IN-N: C17.1 R14.2(N2) U5.C1
IN-P: C17.2(N2) R15.2(N2) U5.D1
LDO_5V: C21.1 E2.2(N2) E3.2(N2) E4.2(N2) E5.2(N2) R27.2(N2) U5.F6 U5.F7 U5.F8
LDO_OUT: R23.1 R27.1
M0: R11.2(N2) R16.2(N2) U5.A7
M1: R10.2(N2) R17.2(N2) U5.A8
MCLK: C3.1 J1.1 R37.2(N2) R38.1 U5.F14(XTAL2_MCLK)
MCLK_FMC: P1.G6 R37.1 R47.2(N2)
MCLK_RETURN: P1.H4 R47.1
REF_N: A1.2 A2.2(V-) C26.2(N2) C27.2(N2) C53.2(N2) R22.1 R36.2(N2) U5.B13
REF_P: C26.1 C27.1 R21.2(N2) R66.2(N2) R67.2(N2) U5.B14
RESET_ADC: C44.1 P4.5 P5.8 R41.2(N2) S1.4(N4) U5.D11
RESET_FPGA: P1.G15 R41.1
SCL: P1.C30 P3.1 U4.6
SCLK: P1.D8 P3.5 P5.4 U5.E11
SDA: P1.C31 P3.2 U4.5
SDI: P1.G9 P3.7 P5.2 U5.E12
SYNC_IN: P1.C10 P4.2 P5.9 R40.2(N2) U5.D12
UNNAMED_3_ADAQ77681V2_I305_M0ADC: R16.1 U5.B7
UNNAMED_3_ADAQ77681V2_I305_M1AD: R17.1 U5.B8
UNNAMED_3_ADAQ77681V2_I305_SYNC: R40.1 U5.D13
UNNAMED_3_ADP2301_I180_BST: C7.1 U1.1
UNNAMED_3_ADP2301_I180_FB: R2.2(N2) R3.1 U1.3
UNNAMED_3_ADP2301_I180_SW: C7.2(N2) D1.C L3.1 U1.6
UNNAMED_3_ADP7182V5_I211_ADJ: R25.1 R26.1 R28.1 U3.2
UNNAMED_3_ADP7182V5_I211_VOUT: C16.2(N2) C23.1 R12.1 R28.2(N2) U3.1(VOUT)
UNNAMED_3_ADR45XX_I443_GND: C39.2(N2) C40.2(N2) R22.2(N2) R49.2(N2) U6.4
UNNAMED_3_ADR45XX_I443_VIN: C40.1 R23.2(N2) R60.2(N2) U6.2
UNNAMED_3_ADR45XX_I443_VOUT: C39.1 R21.1 R55.1 U6.6(VOUT)
UNNAMED_3_CAP_I190_N1: C14.1 U2.2 U2.6
UNNAMED_3_CAP_I191_N1: C11.1 U2.15 U2.19
UNNAMED_3_CAP_I193_N2: C8.2(N2) U2.4
UNNAMED_3_CAP_I203_N1: C2.1 R1.1 U2.9
UNNAMED_3_CAP_I204_N1: C6.1 R4.1 U2.12
UNNAMED_3_CAP_I209_N1: C16.1 R26.2(N2)
UNNAMED_3_IND_I195_N2: L2.2(N2) U2.24
UNNAMED_3_IND_I196_N2: L1.2(N2) U2.21
UNNAMED_3_LINLT3095_I198_OUT1: R52.1 U2.8
UNNAMED_3_LINLT3095_I198_OUT2: R9.1 U2.13
UNNAMED_3_LINLT3095_I198_RT: R8.1 U2.17
UNNAMED_3_RES_I169_N1: R24.1 S1.3
UNNAMED_3_RES_I306_N2: R34.2(N2) S2.1B
UNNAMED_3_RES_I311_N1: R11.1 R32.1 S2.4A
UNNAMED_3_RES_I312_N1: R10.1 R33.1 S2.5A
UNNAMED_3_RES_I360_N2: R38.2(N2) Y1.3
UNNAMED_3_RES_I424_N2: R18.2(N2) S2.2B(N9)
UNNAMED_3_RES_I425_N2: R19.2(N2) S2.3B
UNNAMED_3_SWITCH5_I307_N7: R20.2(N2) S2.4B S2.5B
UNNAMED_6_CN8PA_I42_N1: P4.1 TP9.1(N1)
UNNAMED_6_CN160PCDGHV2_I2_LA11P: P1.H16 R48.1
UNNAMED_6_CN160PCDGHV2_I2_PRSNT: P1.H2 R13.2(N2)
UNNAMED_6_CN160PCDGHV2_I8_LA08P: P1.G12 R46.1
UNNAMED_6_CN160PCDGHV2_I17_3P3V: P1.C39 P1.D36 P1.D38 P1.D40 R56.2(N2)
UNNAMED_6_CN160PCDGHV2_I17_LA09: P1.D14 R45.1
UNNAMED_6_CN160PCDGHV2_I21_LA10: P1.C14 R44.1
UNNAMED_6_ICM24CXX_I24_VCC: R58.2(N2) R59.1 U4.8
VOUT: A1.1(VOUT) A2.1 C54.2(N2) R67.1

Pads without a net: P1 C2 C3 C6 C7 C11 C15 C18 C19 C22 C23 C26 C27 C35 C37 D1 D4 D5 D9 D12 D15 D17 D18 D20 D21 D23 D24 D26 D27 D29 D30 D31 D33 D34 G2 G3 G7 G10 G13 G16 G18 G19 G21 G22 G24 G25 G27 G28 G30 G31 G33 G34 G36 G37 G39 H1 H5 H8 H11 H14 H17 H19 H20 H22 H23 H25 H26 H28 H29 H31 H32 H34 H35 H37 H38 H40; P2 1 2 3; P3 3; U3 4; U5 A9 A10 A12 B5 B6 B12 C5 D8 E2 E5 E6; U6 1 3 5 7 8

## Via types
v1: diameter 0.51, hole 0.249, TOP to BOTTOM, 299 vias
v2: diameter 0.406, hole 0.203, TOP to BOTTOM, 20 vias
v3: diameter 0.759, hole 0.409, TOP to BOTTOM, 13 vias
v4: diameter 1.021, hole 0.51, TOP to BOTTOM, 4 vias

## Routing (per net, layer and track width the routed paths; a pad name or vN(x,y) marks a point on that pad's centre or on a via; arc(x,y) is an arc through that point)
3V3: length 58.8
  TOP w0.2: U5.C8 v2(26.5,34.8)
  TOP w0.25: U2.10 37.25,53.17 v1(37.5,52.93) 37.75,53.17 U2.11
  TOP w0.5: R59.2 68.5,21.05 v3(66.5,19.05) ; R20.1 v3(32.58,22.91) ; R19.1 v3(30.04,22.91) ; R18.1 v3(27.5,22.91) ; R34.1 v3(24.96,22.91)
  TOP w0.8: R56.1 v3(67,13.55) ; E1.2 v3(29.05,28) ; R24.2 v3(57.38,13)
  L3_PWR w0.5: P5.12 60.08,66.25 ; P5.12 58.96,65.13 ; P5.12 57.84,66.25 ; P5.12 58.96,67.37 ; 31.9,33.43 31.9,33.57 30.04,35.42 27.12,35.42 v2(26.5,34.8) ; P5.6 61.5,67.37 ; P5.6 62.62,66.25 ; P5.6 61.5,65.13 ; P5.6 60.38,66.25
  L3_PWR w0.8: 31.9,33.43 32.62,32.71 32.62,27.93
  BOTTOM w0.4: Y1.4 Y1.1 46.4,27.65 C25.1 v3(45.95,26.25)
  BOTTOM w0.5: v1(37.5,66.18) 37.5,62.93 39.12,61.3 39.12,53.93 38.12,52.93 v1(37.5,52.93)
  BOTTOM w0.8: v4(10.55,29.1) 11.55,30.1 P2.4
  vias: v1(26.88,61.43) v1(26.88,60.8) v1(26.88,60.18) v1(27.5,61.43) v1(27.5,60.8) v1(27.5,60.18) v1(28.12,61.43) v1(28.12,60.8) v1(28.12,60.18) v1(36.88,67.43) v1(36.88,66.8) v1(36.88,66.18) v1(37.5,67.43) v1(37.5,66.8) v1(38.12,67.43) v1(38.12,66.8) v1(38.12,66.18) v1(51,62.8) v1(51,62.18) v1(51,61.43) v1(51.62,62.8) v1(51.62,62.18) v1(51.62,61.43) v1(52.38,62.8) v1(52.38,62.18) v1(52.38,61.43)
3V3_AUX: length 2.3
  TOP w0.5: R58.1 72,20.8 v1(72.75,20.05)
  BOTTOM w0.5: P1.D32 73.61,20.05 v1(72.75,20.05)
5V3: length 47.9
  TOP w0.14: U5.B9 27.3,35.6 27.3,34.8 U5.D9
  TOP w0.2: U5.B9 v2(28.1,36.4) U5.B10 v2(28.9,36.4) U5.B11
  L3_PWR w0.5: v2(28.1,36.4) v2(28.9,36.4)
  L3_PWR w0.8: UNK5V.1 35.13,38.85 v3(35.13,37.71) 35.13,35.32 34.3,34.49 32.47,34.49 30.56,36.4 v2(28.9,36.4)
  BOTTOM w0.5: v3(35.13,37.71) 36.11,37.71 40.17,33.65 R60.1 ; R35.2 31.43,51.54 29.8,49.92 UNK5V.1
15V: length 42.1
  TOP w0.2: U5.D4 v1(23.3,34)
  TOP w0.25: U5.E4 v1(23.3,34) ; v1(23.3,34) U5.D3 ; v1(23.3,34) U5.E3
  L3_PWR w0.5: 19.72,37.45 21.42,35.75 21.55,35.75 v1(23.3,34)
  L3_PWR w0.8: UNK15V.1 43.76,48.89 24.34,48.89 19.72,44.27 19.72,37.45
  BOTTOM w0.8: C18.1 22.45,34 v1(23.3,34)
-15V: length 12.9
  TOP w0.25: U5.B3 v1(23.3,35.6) ; v1(23.3,35.6) U5.C3 ; v1(23.3,35.6) U5.B4 ; v1(23.3,35.6) U5.C4
  L3_PWR w0.8: UNK-15V.1 22,36.9 v1(23.3,35.6)
  BOTTOM w0.8: C19.1 22.5,35.6 v1(23.3,35.6)
-16V: length 20.5
  TOP w0.3: R3.2 v1(27.38,55.8)
  TOP w0.503: U1.2 v1(24.75,56.79)
  BOTTOM w0.5: v1(17.75,56.8) 23.25,56.8 24.25,55.8 v1(27.38,55.8) ; v1(25.12,65.55) 24.75,65.18 v1(24.75,56.79)
GND_SIGNAL: length 617.7
  TOP w0.2: v2(25.7,34.8) U5.D6 U5.D5 ; v2(25.7,34.8) U5.C7 ; v2(25.7,34.8) U5.C6 ; U5.A5 v2(24.1,36.4)
  TOP w0.25: U5.F11 v2(29.3,32.1) ; U5.B1 U5.B2 U5.C2 U5.D2 U5.E1 ; v2(31.65,32.1) 31.6,32.1 U5.F13 ; U5.D7 v2(25.7,34.8) ; U5.C13 U5.C12 v2(29.69,34.79) ; 34.5,55.3 35,55.8 U2.5 37.5,55.8 ; 37.5,55.8 U2.PAD ; 37.5,55.8 U2.16 40.12,55.8 40.5,55.43 ; 24.09,37.4 24.09,37.71 ; 39.88,54.3 39.37,54.8 U2.14 ; U2.3 v1(37,56.8) ; 35.12,54.3 35.63,54.8 U2.7 ; v2(28.42,32.08) 28.5,32.16 U5.F10 ; U2.18 v1(38,56.8) ; U5.A6 U5.A5
  TOP w0.254: 22.49,37.19 U5.A2 21.71,37.19 ; 24.11,37.19 U5.A5 ; 20.91,36.41 U5.A1 ; U5.A1 21.69,37.19 ; U5.A1 20.91,37.19 ; 20.82,33.6 U5.E1 20.91,33.21 ; 24.09,37.19 U5.A4 23.31,37.19 ; 20.91,36.39 U5.B1 20.82,36 ; 23.29,37.19 U5.A3 22.51,37.19
  TOP w0.35: R13.1 v1(64.47,58.05)
  TOP w0.4: R53.2 v1(13.5,27.93) ; R54.2 v1(13.5,41.43)
  TOP w0.5: J3.5 1.7,22.44 ; J3.5 1.7,19.81 ; J3.5 3.01,21.13 ; 52.42,14 S1.2 ; S1.2 v1(52.42,15.37) ; S1.2 53.1,14.66 ; S1.2 51.74,14.66 ; C44.2 52.58,17.25 ; C44.2 53.25,16.55 ; C44.2 v1(51.85,16.55) ; C44.2 52.58,15.85 ; S1.1 53.1,11.44 ; S1.1 52.42,10.79 ; S1.1 v1(51.68,11.44) ; S1.1 52.42,12.1 ; R4.2 40,48.75 ; R4.2 40.67,48.05 ; R4.2 40,47.35 ; 6.8,41.81 J4.4 ; J4.4 8.11,43.13 ; J4.4 6.8,44.44 ; 12.8,40.55 R54.2 14.2,40.55 ; 5.49,48.23 J4.3 ; J4.3 6.8,46.91 ; J4.3 8.11,48.23 ; J4.3 6.8,49.54 ; 1.7,44.44 J4.5 1.7,41.81 ; 43.5,11.49 GND4.1 ; GND4.1 42.44,12.55 ; GND4.1 44.56,12.55 ; GND4.1 43.5,13.61 ; 61.5,62.59 P5.5 ; P5.5 61.5,64.83 ; P5.5 60.38,63.71 ; P5.5 62.62,63.71 ; J3.4 8.11,21.13 ; J3.4 5.49,21.13 ; J3.4 6.8,22.44 ; J3.4 6.8,19.81 ; 34.58,48.05 R1.2 ; R1.2 35.25,48.75 ; R1.2 35.25,47.35 ; 34.58,49.8 C2.2 ; C2.2 35.25,49.1 ; C2.2 35.25,50.5 ; 17.25,12.74 GND2.1 ; GND2.1 17.25,14.86 ; GND2.1 18.31,13.8 ; GND2.1 16.19,13.8 ; J1.2 42.76,23.45 ; J1.2 41.45,24.76 ; J1.2 40.14,23.45 ; J1.2 41.45,22.14 ; J4.2 3.01,48.23 ; J4.2 1.7,49.54 ; J4.2 1.7,46.91 ; GND1.1 50.56,57.55 ; GND1.1 49.5,56.49 ; GND1.1 49.5,58.61 ; GND1.1 48.44,57.55 ; 12.8,29.05 R53.2 14.2,29.05 ; 45.24,23.45 J1.3 ; J1.3 47.86,23.45 ; J1.3 46.55,24.76 ; J1.3 46.55,22.14 ; 40,49.1 C6.2 40,50.5 ; 41.25,52.93 39.88,54.3 ; 36.25,34.85 C34.2 36.92,35.55 ; 4.25,33.62 P7.2 ; P7.2 5.37,34.74 ; P7.2 3.13,34.74 ; P7.2 4.25,35.86 ; 45.24,18.35 J1.4 ; J1.4 46.55,19.66 ; J1.4 47.86,18.35 ; J1.4 46.55,17.04 ; 58.96,62.59 P5.11 ; P5.11 58.96,64.83 ; P5.11 57.84,63.71 ; P5.11 60.08,63.71 ; P14.2 49.69,66.24 ; P14.2 50.88,65.05 ; P14.2 48.5,65.05 ; P14.2 49.69,63.86 ; 24.84,44.17 GND3.1 ; GND3.1 26.96,44.17 ; GND3.1 25.9,45.23 ; GND3.1 25.9,43.12 ; 33.6,40.71 R36.1 ; R36.1 32.9,41.38 ; R36.1 34.3,41.38 ; R36.1 33.6,42.05 ; 40.14,18.35 J1.5 ; J1.5 41.45,19.66 ; J1.5 41.45,17.04 ; J1.5 42.76,18.35 ; 1.7,27.54 J3.2 1.7,24.91 ; 77.11,19.39 U4.3 76.51,20.77 ; C4.2 v1(44.5,63.32) ; C4.2 43.8,64.05 ; C4.2 45.2,64.05 ; 36.92,33.8 C35.2 36.25,34.5 ; U4.4 78.38,19.39 ; U4.4 77.18,19.39 ; U4.4 77.78,20.77 ; J3.3 6.8,27.54 ; J3.3 8.11,26.23 ; J3.3 6.8,24.91 ; 33.75,52.93 35.12,54.3
  TOP w0.6: U4.3 v1(76.51,17.89) ; U4.4 v1(77.78,17.89)
  L2_GND w0.5: 25.9,43.12 GND3.1 ; GND3.1 24.84,44.17 ; GND3.1 25.9,45.23 ; GND3.1 26.96,44.17 ; 60.38,63.71 P5.5 ; P5.5 61.5,64.83 ; P5.5 61.5,62.59 ; P5.5 62.62,63.71 ; GND4.1 43.5,13.61 ; GND4.1 42.44,12.55 ; GND4.1 43.5,11.49 ; GND4.1 44.56,12.55 ; 41.45,22.14 J1.2 ; J1.2 40.14,23.45 ; J1.2 42.76,23.45 ; J1.2 41.45,24.76 ; P5.11 58.96,64.83 ; P5.11 60.08,63.71 ; P5.11 57.84,63.71 ; P5.11 58.96,62.59 ; J1.5 42.76,18.35 ; J1.5 41.45,17.04 ; J1.5 41.45,19.66 ; J1.5 40.14,18.35 ; J4.2 3.01,48.23 ; J4.2 1.7,46.91 ; J4.2 1.7,49.54 ; 6.8,24.91 J3.3 ; J3.3 6.8,27.54 ; J3.3 8.11,26.23 ; 1.7,44.44 J4.5 1.7,41.81 ; 3.13,34.74 P7.2 ; P7.2 4.25,35.86 ; P7.2 4.25,33.62 ; P7.2 5.37,34.74 ; GND2.1 17.25,14.86 ; GND2.1 18.31,13.8 ; GND2.1 17.25,12.74 ; GND2.1 16.19,13.8 ; 6.8,41.81 J4.4 ; J4.4 6.8,44.44 ; J4.4 8.11,43.13 ; GND1.1 49.5,58.61 ; GND1.1 50.56,57.55 ; GND1.1 48.44,57.55 ; GND1.1 49.5,56.49 ; J3.4 6.8,22.44 ; J3.4 5.49,21.13 ; J3.4 6.8,19.81 ; J3.4 8.11,21.13 ; P14.2 49.69,66.24 ; P14.2 49.69,63.86 ; P14.2 48.5,65.05 ; P14.2 50.88,65.05 ; 5.49,48.23 J4.3 ; J4.3 6.8,46.91 ; J4.3 6.8,49.54 ; J4.3 8.11,48.23 ; J1.3 46.55,24.76 ; J1.3 47.86,23.45 ; J1.3 46.55,22.14 ; J1.3 45.24,23.45 ; J1.4 46.55,19.66 ; J1.4 45.24,18.35 ; J1.4 46.55,17.04 ; J1.4 47.86,18.35 ; 1.7,27.54 J3.2 1.7,24.91 ; J3.5 3.01,21.13 ; J3.5 1.7,22.44 ; J3.5 1.7,19.81
  L3_PWR w0.5: 46.55,22.14 J1.3 ; J1.3 46.55,24.76 ; J1.3 47.86,23.45 ; J1.3 45.24,23.45 ; 1.7,27.54 J3.2 1.7,24.91 ; 6.8,46.91 J4.3 ; J4.3 6.8,49.54 ; J4.3 5.49,48.23 ; J4.3 8.11,48.23 ; J1.4 47.86,18.35 ; J1.4 46.55,17.04 ; J1.4 45.24,18.35 ; J1.4 46.55,19.66 ; J3.3 8.11,26.23 ; J3.3 6.8,24.91 ; J3.3 6.8,27.54 ; P7.2 5.37,34.74 ; P7.2 3.13,34.74 ; P7.2 4.25,33.62 ; P7.2 4.25,35.86 ; GND3.1 26.96,44.17 ; GND3.1 25.9,45.23 ; GND3.1 24.84,44.17 ; GND3.1 25.9,43.12 ; J3.5 1.7,22.44 ; J3.5 1.7,19.81 ; J3.5 3.01,21.13 ; 41.45,22.14 J1.2 ; J1.2 41.45,24.76 ; J1.2 40.14,23.45 ; J1.2 42.76,23.45 ; J1.5 42.76,18.35 ; J1.5 40.14,18.35 ; J1.5 41.45,17.04 ; J1.5 41.45,19.66 ; 1.7,41.81 J4.5 1.7,44.44 ; J4.2 3.01,48.23 ; J4.2 1.7,46.91 ; J4.2 1.7,49.54 ; 5.49,21.13 J3.4 ; J3.4 8.11,21.13 ; J3.4 6.8,22.44 ; J3.4 6.8,19.81 ; GND1.1 50.56,57.55 ; GND1.1 49.5,58.61 ; GND1.1 49.5,56.49 ; GND1.1 48.44,57.55 ; J4.4 8.11,43.13 ; J4.4 6.8,41.81 ; J4.4 6.8,44.44
  BOTTOM w0.254: 74.51,44.84 P1.C12 ; P1.C12 75.49,44.84 ; P1.C12 74.51,45.82 ; P1.C12 75.49,45.82 ; P1.G14 70.41,42.3 ; P1.G14 69.43,43.28 ; P1.G14 70.41,43.28 ; P1.G14 69.43,42.3 ; P1.C21 75.49,34.39 ; P1.C21 74.51,33.41 ; P1.C21 74.51,34.39 ; P1.C21 75.49,33.41 ; P1.C13 75.49,43.57 ; P1.C13 74.51,44.55 ; P1.C13 74.51,43.57 ; P1.C13 75.49,44.55 ; P1.D25 74.22,29.31 ; P1.D25 74.22,28.33 ; P1.D25 73.24,28.33 ; P1.D25 73.24,29.31 ; P1.G1 70.41,59.79 ; P1.G1 69.43,59.79 ; P1.G1 69.43,58.81 ; P1.G1 70.41,58.81 ; 74.51,14.36 P1.C36 ; P1.C36 75.49,15.34 ; P1.C36 75.49,14.36 ; P1.C36 74.51,15.34 ; 69.43,38.49 P1.G17 ; P1.G17 69.43,39.47 ; P1.G17 70.41,39.47 ; P1.G17 70.41,38.49 ; 68.16,21.98 P1.H30 ; P1.H30 68.16,22.96 ; P1.H30 69.14,21.98 ; P1.H30 69.14,22.96 ; P1.C25 75.49,28.33 ; P1.C25 74.51,28.33 ; P1.C25 74.51,29.31 ; P1.C25 75.49,29.31 ; 69.43,20.42 P1.G32 70.41,20.42 ; P1.H18 69.14,37.22 ; P1.H18 69.14,38.2 ; P1.H18 68.16,37.22 ; P1.H18 68.16,38.2 ; P1.D13 74.22,43.57 ; P1.D13 74.22,44.55 ; P1.D13 73.24,44.55 ; P1.D13 73.24,43.57 ; P1.G20 70.41,35.66 ; P1.G20 69.43,34.68 ; P1.G20 69.43,35.66 ; P1.G20 70.41,34.68 ; P1.D6 74.22,53.44 ; P1.D6 73.24,53.44 ; P1.D6 73.24,52.46 ; P1.D6 74.22,52.46 ; 69.43,16.61 P1.G35 ; P1.G35 70.41,16.61 ; P1.G35 69.43,15.63 ; P1.G35 70.41,15.63 ; 69.43,28.04 P1.G26 ; P1.G26 70.41,28.04 ; P1.G26 69.43,27.06 ; P1.G26 70.41,27.06 ; P1.G23 70.41,31.85 ; P1.G23 69.43,30.87 ; P1.G23 70.41,30.87 ; P1.G23 69.43,31.85 ; 69.14,53.44 P1.H6 68.16,53.44 ; P1.H24 69.14,30.58 ; P1.H24 69.14,29.6 ; P1.H24 68.16,30.58 ; P1.H24 68.16,29.6 ; P1.G29 70.41,23.25 ; P1.G29 69.43,23.25 ; P1.G29 69.43,24.23 ; P1.G29 70.41,24.23 ; 74.51,58.81 P1.C1 ; P1.C1 75.49,58.81 ; P1.C1 75.49,59.79 ; P1.C1 74.51,59.79 ; P1.H36 69.14,14.36 ; P1.H36 68.16,14.36 ; P1.H36 69.14,15.34 ; P1.H36 68.16,15.34 ; P1.G11 70.41,47.09 ; P1.G11 69.43,46.11 ; P1.G11 69.43,47.09 ; P1.G11 70.41,46.11 ; P1.G5 70.41,53.73 ; P1.G5 69.43,53.73 ; P1.G5 69.43,54.71 ; P1.G5 70.41,54.71 ; P1.G4 70.41,55 ; P1.G4 70.41,55.98 ; P1.G4 69.43,55 ; P1.G4 69.43,55.98 ; P1.C33 75.49,18.17 ; P1.C33 74.51,19.15 ; P1.C33 75.49,19.15 ; 74.51,29.6 P1.C24 ; P1.C24 75.49,30.58 ; P1.C24 75.49,29.6 ; P1.C24 74.51,30.58 ; 74.51,25.5 P1.C28 ; P1.C28 74.51,24.52 ; P1.C28 75.49,24.52 ; P1.C28 75.49,25.5 ; P1.C17 75.49,38.49 ; P1.C17 75.49,39.47 ; P1.C17 74.51,39.47 ; P1.C17 74.51,38.49 ; 74.51,10.26 P1.C40 ; P1.C40 74.51,9.28 ; P1.C40 75.49,10.26 ; P1.C40 75.49,9.28 ; 73.24,24.52 P1.D28 ; P1.D28 74.22,25.5 ; P1.D28 74.22,24.52 ; P1.D28 73.24,25.5 ; P1.D16 74.22,40.74 ; P1.D16 74.22,39.76 ; P1.D16 73.24,39.76 ; P1.D16 73.24,40.74 ; P1.C38 75.49,12.8 ; P1.C38 75.49,11.82 ; P1.C38 74.51,12.8 ; 68.16,48.65 P1.H9 69.14,48.65 ; P1.D37 74.22,13.09 ; P1.D37 73.24,13.09 ; P1.D37 73.24,14.07 ; P1.D37 74.22,14.07 ; P1.H21 69.14,34.39 ; P1.H21 69.14,33.41 ; P1.H21 68.16,34.39 ; P1.H21 68.16,33.41 ; P1.H39 69.14,11.53 ; P1.H39 68.16,10.55 ; P1.H39 69.14,10.55 ; P1.H39 68.16,11.53 ; 73.24,33.12 P1.D22 ; P1.D22 74.22,33.12 ; P1.D22 74.22,32.14 ; P1.D22 73.24,32.14 ; 68.16,42.01 P1.H15 ; P1.H15 68.16,41.03 ; P1.H15 69.14,41.03 ; P1.H15 69.14,42.01 ; P1.C5 75.49,53.73 ; P1.C5 74.51,53.73 ; P1.C5 75.49,54.71 ; P1.C5 74.51,54.71 ; P1.H27 69.14,25.79 ; P1.H27 68.16,26.77 ; P1.H27 69.14,26.77 ; P1.H27 68.16,25.79 ; 74.51,24.23 P1.C29 ; P1.C29 75.49,24.23 ; P1.C29 75.49,23.25 ; P1.C29 74.51,23.25 ; P1.D19 74.22,35.95 ; P1.D19 74.22,36.93 ; P1.D19 73.24,35.95 ; P1.D19 73.24,36.93 ; P1.C32 75.49,20.42 ; P1.C32 74.51,19.44 ; P1.C32 74.51,20.42 ; P1.C32 75.49,19.44 ; P1.H12 69.14,45.82 ; P1.H12 69.14,44.84 ; P1.H12 68.16,45.82 ; P1.C16 75.49,40.74 ; P1.C16 75.49,39.76 ; P1.C16 74.51,40.74 ; P1.C16 74.51,39.76 ; 74.51,35.66 P1.C20 ; P1.C20 74.51,34.68 ; P1.C20 75.49,35.66 ; P1.C20 75.49,34.68 ; 69.43,11.82 P1.G38 ; P1.G38 70.41,12.8 ; P1.G38 70.41,11.82 ; P1.G38 69.43,12.8 ; P1.G40 70.41,10.26 ; P1.G40 70.41,9.28 ; P1.G40 69.43,9.28 ; P1.G40 69.43,10.26 ; 74.51,55 P1.C4 ; P1.C4 74.51,55.98 ; P1.C4 75.49,55 ; P1.C4 75.49,55.98 ; 73.24,56.27 P1.D3 ; P1.D3 74.22,56.27 ; P1.D3 74.22,57.25 ; P1.D3 73.24,57.25 ; 73.24,11.53 P1.D39 ; P1.D39 74.22,10.55 ; P1.D39 73.24,10.55 ; P1.D2 74.22,58.52 ; P1.D2 73.24,57.54 ; P1.D2 73.24,58.52 ; P1.D2 74.22,57.54 ; P1.H3 69.14,56.27 ; P1.H3 69.14,57.25 ; P1.H3 68.16,57.25 ; P1.H3 68.16,56.27 ; P1.D7 74.22,52.17 ; P1.D7 73.24,51.19 ; P1.D7 73.24,52.17
  BOTTOM w0.35: P1.C8 v1(75.73,50.41)
  BOTTOM w0.5: P14.2 49.69,66.24 ; P14.2 50.88,65.05 ; P14.2 48.5,65.05 ; P14.2 49.69,63.86 ; 40.9,51.54 C20.2 ; C20.2 41.6,52.21 ; C20.2 41.6,50.87 ; C20.2 42.3,51.54 ; 24.22,8.05 R29.2 ; R29.2 24.92,8.72 ; R29.2 25.62,8.05 ; R29.2 v1(24.92,7.32) ; R33.2 35.08,8.72 ; R33.2 v1(35.08,7.32) ; R33.2 34.38,8.05 ; R33.2 35.78,8.05 ; 6.8,19.81 J3.4 ; J3.4 8.11,21.13 ; J3.4 6.8,22.44 ; J3.4 5.49,21.13 ; 1.7,41.81 J4.5 1.7,44.44 ; R31.2 v1(30,7.32) ; R31.2 29.3,8.05 ; R31.2 30,8.72 ; R31.2 30.7,8.05 ; R32.2 v1(32.54,7.32) ; R32.2 33.24,8.05 ; R32.2 31.84,8.05 ; R32.2 32.54,8.72 ; GND2.1 18.31,13.8 ; GND2.1 16.19,13.8 ; GND2.1 17.25,14.86 ; GND2.1 17.25,12.74 ; v1(20,36.1) 20.81,36.1 ; v1(20,36.1) 19.19,36.1 ; v1(20,36.1) 20,37.03 ; 25.9,43.12 GND3.1 ; GND3.1 24.84,44.17 ; GND3.1 26.96,44.17 ; GND3.1 25.9,45.23 ; P7.2 4.25,35.86 ; P7.2 5.37,34.74 ; P7.2 4.25,33.62 ; P7.2 3.13,34.74 ; Y1.2 44.2,30 ; Y1.2 44.2,28.2 ; Y1.2 45.2,29.1 ; Y1.2 43.2,29.1 ; R30.2 27.46,8.72 ; R30.2 v1(27.46,7.32) ; R30.2 26.76,8.05 ; R30.2 28.16,8.05 ; 6.8,46.91 J4.3 ; J4.3 8.11,48.23 ; J4.3 6.8,49.54 ; J4.3 5.49,48.23 ; 10.03,21.55 P2.7 ; P2.7 12.04,22.48 ; P2.7 10.03,23.41 ; P2.7 8.02,22.48 ; 24.52,35.35 C24.2 ; C24.2 25.22,36.02 ; C24.2 25.22,34.68 ; C24.2 25.92,35.35 ; J3.3 6.8,27.54 ; J3.3 6.8,24.91 ; J3.3 8.11,26.23 ; P1.G8 v1(70.65,50.41) ; J3.5 1.7,22.44 ; J3.5 1.7,19.81 ; J3.5 3.01,21.13 ; 26.78,30.55 v1(27.48,30.55) ; v1(27.48,30.55) 27.48,31.22 ; v1(27.48,30.55) 28.17,30.55 ; v1(20,33.55) 20.81,33.55 ; v1(20,33.55) 19.19,33.55 ; v1(20,33.55) 20,32.62 ; 42.44,12.55 GND4.1 ; GND4.1 43.5,11.49 ; GND4.1 43.5,13.61 ; GND4.1 44.56,12.55 ; GND1.1 50.56,57.55 ; GND1.1 49.5,58.61 ; GND1.1 48.44,57.55 ; GND1.1 49.5,56.49 ; 40.68,38.35 R49.1 ; R49.1 41.36,37.65 ; R49.1 41.36,39.04 ; R49.1 42.03,38.35 ; v1(25.5,30.55) 25.5,31.22 ; v1(25.5,30.55) 25.5,29.88 ; v1(25.5,30.55) 26.2,30.55 ; J1.2 41.45,24.76 ; J1.2 42.76,23.45 ; J1.2 41.45,22.14 ; J1.2 40.14,23.45 ; 44.45,26.5 C25.2 ; C25.2 43.78,27.2 ; C25.2 45.12,27.2 ; C25.2 44.45,27.9 ; J4.2 1.7,49.54 ; J4.2 1.7,46.91 ; J4.2 3.01,48.23 ; 29.25,38.63 v1(29.25,39.3) ; v1(29.25,39.3) 29.25,39.97 ; v1(29.25,39.3) 29.95,39.3 ; v1(29.25,39.3) 28.55,39.3 ; J1.4 47.86,18.35 ; J1.4 45.24,18.35 ; J1.4 46.55,19.66 ; J1.4 46.55,17.04 ; 1.7,24.91 J3.2 1.7,27.54 ; 31.65,31.4 v2(31.65,32.1) ; v2(31.65,32.1) 31.65,32.8 ; v2(31.65,32.1) 30.98,32.1 ; 57.84,63.71 P5.11 ; P5.11 60.08,63.71 ; P5.11 58.96,64.83 ; P5.11 58.96,62.59 ; P3.4 63.22,39.25 ; P3.4 v1(59.14,39.25) ; P3.4 61.21,38.32 ; P2.6 12.95,25.95 ; P2.6 10.94,25.02 ; P2.6 12.95,24.09 ; P2.6 14.96,25.02 ; P5.5 62.62,63.71 ; P5.5 60.38,63.71 ; P5.5 61.5,62.59 ; P5.5 61.5,64.83 ; v1(34.9,29.55) 35.6,29.55 ; v1(34.9,29.55) 34.9,28.88 ; v1(34.9,29.55) 34.9,30.22 ; 31.65,29.6 v2(31.65,30.3) ; v2(31.65,30.3) 31.65,31 ; v2(31.65,30.3) 30.98,30.3 ; 41.45,17.04 J1.5 ; J1.5 42.76,18.35 ; J1.5 41.45,19.66 ; J1.5 40.14,18.35 ; 33.4,36.48 v1(33.4,37.15) ; v1(33.4,37.15) 34.1,37.15 ; v1(33.4,37.15) 33.4,37.82 ; 23.8,29.88 v1(23.8,30.55) ; v1(23.8,30.55) 23.1,30.55 ; v1(23.8,30.55) 23.8,31.22 ; 45.24,23.45 J1.3 ; J1.3 47.86,23.45 ; J1.3 46.55,22.14 ; J1.3 46.55,24.76 ; 6.8,41.81 J4.4 ; J4.4 6.8,44.44 ; J4.4 8.11,43.13 ; P1.C9 v1(75.73,49.14) ; P1.D10 v1(73,47.87) ; P1.H33 v1(67.92,18.66)
  vias: v1(16.88,54.55) v1(16.88,53.68) v1(16.88,52.8) v1(17.25,58.43) v1(17.38,63.05) v1(17.38,62.3) v1(17.38,61.55) v1(17.38,60.8) v1(17.38,60.05) v1(17.51,63.93) v1(17.65,59.3) v1(17.75,53.82) v1(18.44,53.66) v1(18.49,61.93) v1(20.85,37.25) v1(21.72,47.55) v1(21.75,54.93) v1(21.88,53.93) v1(21.88,52.93) v1(22.38,54.93) v1(22.75,53.93) v1(22.9,37.33) v1(23.11,55.8) v1(23.12,55.05) v1(27.25,65.43) v1(27.25,64.78) v1(28,64.8) v1(31,53.18) v1(31,52.55) v1(31.75,53.18) v1(31.75,52.55) v1(32.25,60.68) v1(32.25,60.05) v1(32.25,59.43) v1(32.38,53.18) v1(32.38,52.55) v1(32.58,39.74) v1(32.88,60.68) v1(32.88,60.05) v1(32.88,59.43) v1(33.6,42.54) v1(34.11,38.09) v1(34.36,49.78) v1(34.54,50.67) v1(35,42.79) v1(35.25,50.66) v1(35.25,46.98) v1(35.76,43.81) v1(37,57.55) v1(37,56.05) v1(37,55.3) v1(37,54.55) v1(37.08,33.77) v1(37.15,35.04) v1(37.79,43.55) v1(38,57.55) v1(38,56.05) v1(38,55.3) v1(38,54.55) v1(38.68,43.55) v1(39.95,42.66) v1(40.46,38.98) v1(40.46,37.84) v1(41.85,52.82) v1(42.12,60.68) v1(42.12,60.05) v1(42.12,59.43) v1(42.11,47.62) v1(42.11,46.98) v1(42.36,52.82) v1(42.75,60.68) v1(42.75,60.05) v1(42.75,59.43) v1(43,43.17) v1(43.88,53.3) v1(44.14,35.55) v1(44.5,53.68) v1(45,53.18) v1(45,52.43) v1(45.03,35.55) v1(45.75,53.18) v1(45.75,52.43) v1(49.5,60.05) v1(49.75,60.55) v1(50.02,60.05) v1(65.75,25.8) v1(67.92,56.76) v1(67.92,52.95) v1(67.92,49.14) v1(67.92,45.33) v1(67.92,41.52) v1(67.92,37.71) v1(67.92,33.9) v1(67.92,30.09) v1(67.92,26.28) v1(67.92,22.47) v1(67.92,14.85) v1(67.92,11.04) v1(70.65,59.3) v1(70.65,55.49) v1(70.65,54.22) v1(70.65,46.6) v1(70.65,42.79) v1(70.65,38.98) v1(70.65,35.17) v1(70.65,31.36) v1(70.65,27.55) v1(70.65,23.74) v1(70.65,19.93) v1(70.65,16.12) v1(70.65,12.31) v1(70.65,9.77) v1(73,58.03) v1(73,56.76) v1(73,52.95) v1(73,51.68) v1(73,44.06) v1(73,40.25) v1(73,36.44) v1(73,32.63) v1(73,28.82) v1(73,25.01) v1(73,13.58) v1(73,11.04) v1(75.62,25.8) v1(75.73,59.3) v1(75.73,55.49) v1(75.73,54.22) v1(75.73,45.33) v1(75.73,44.06) v1(75.73,40.25) v1(75.73,38.98) v1(75.73,35.17) v1(75.73,33.9) v1(75.73,30.09) v1(75.73,28.82) v1(75.73,14.85) v1(75.73,12.31) v1(75.73,9.77) v3(44.45,26.35) v4(7.85,24.02) v4(12.87,22.29) v4(15.67,24.06)
VDD2_ADC: length 8
  TOP w0.2: v1(33.4,35.65) 32.95,35.2 U5.C14
  TOP w0.25: U5.A14 v1(32.2,37.3)
  L3_PWR w0.8: v3(31.75,39.18) 32.2,38.73 v1(32.2,37.3) 32.2,36.4 32.95,35.65 v1(33.4,35.65)
  BOTTOM w0.8: E3.1 30.95,39.18 v3(31.75,39.18)
VDD2_PGA: length 5
  TOP w0.25: U5.F4 23.7,32.15 v1(23.8,32.05) 24.13,32.05 24.5,32.42 U5.F5
  L3_PWR w0.8: v1(23.8,32.05) 22.5,30.75 v1(22.5,29.6)
VDD_ADC: length 10.7
  TOP w0.25: v1(29.25,37.8) 29.3,37.75 U5.A11 ; U5.A13 v1(30.9,37.9)
  L3_PWR w0.7: 30.09,37.9 30.09,39.5 30.01,39.59 30.01,39.61 29.56,40.06 28.24,40.06 27.43,39.25 v3(26.5,39.25)
  L3_PWR w0.8: v1(29.25,37.8) 29.35,37.9 v1(30.9,37.9)
  BOTTOM w0.8: v3(26.5,39.25) E2.1
VDD_FDA: length 8.8
  TOP w0.2: U5.E9 v2(27.3,34) ; U5.E7 v2(26.5,34)
  TOP w0.25: v2(27.3,34) U5.E8 v2(26.5,34)
  L3_PWR w0.5: v2(27.3,34) v2(26.5,34) 26.5,33.2
  L3_PWR w0.8: v1(26.5,29.6) 26.5,33.2
  BOTTOM w0.4: C24.1 26.35,33.85 v2(26.5,34)
VDD_IO: length 3.9
  TOP w0.25: v1(27.48,32.05) 27.48,32.58 U5.F9
  L3_PWR w0.8: v1(27.48,32.05) 27.48,31.89 28.47,30.9 28.47,30.07 v1(28,29.6)
